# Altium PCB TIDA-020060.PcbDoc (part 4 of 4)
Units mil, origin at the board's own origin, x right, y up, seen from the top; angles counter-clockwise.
Board outline 2114.94 x 3612.21 mil, 4 copper layers (Top Layer, Signal Layer 1, Signal Layer 2, Bottom Layer), stack 61.811 mil thick; 272 components, 167 nets, 840 pads, 352 vias.
Unrouted connection lines stored in the file: 261.
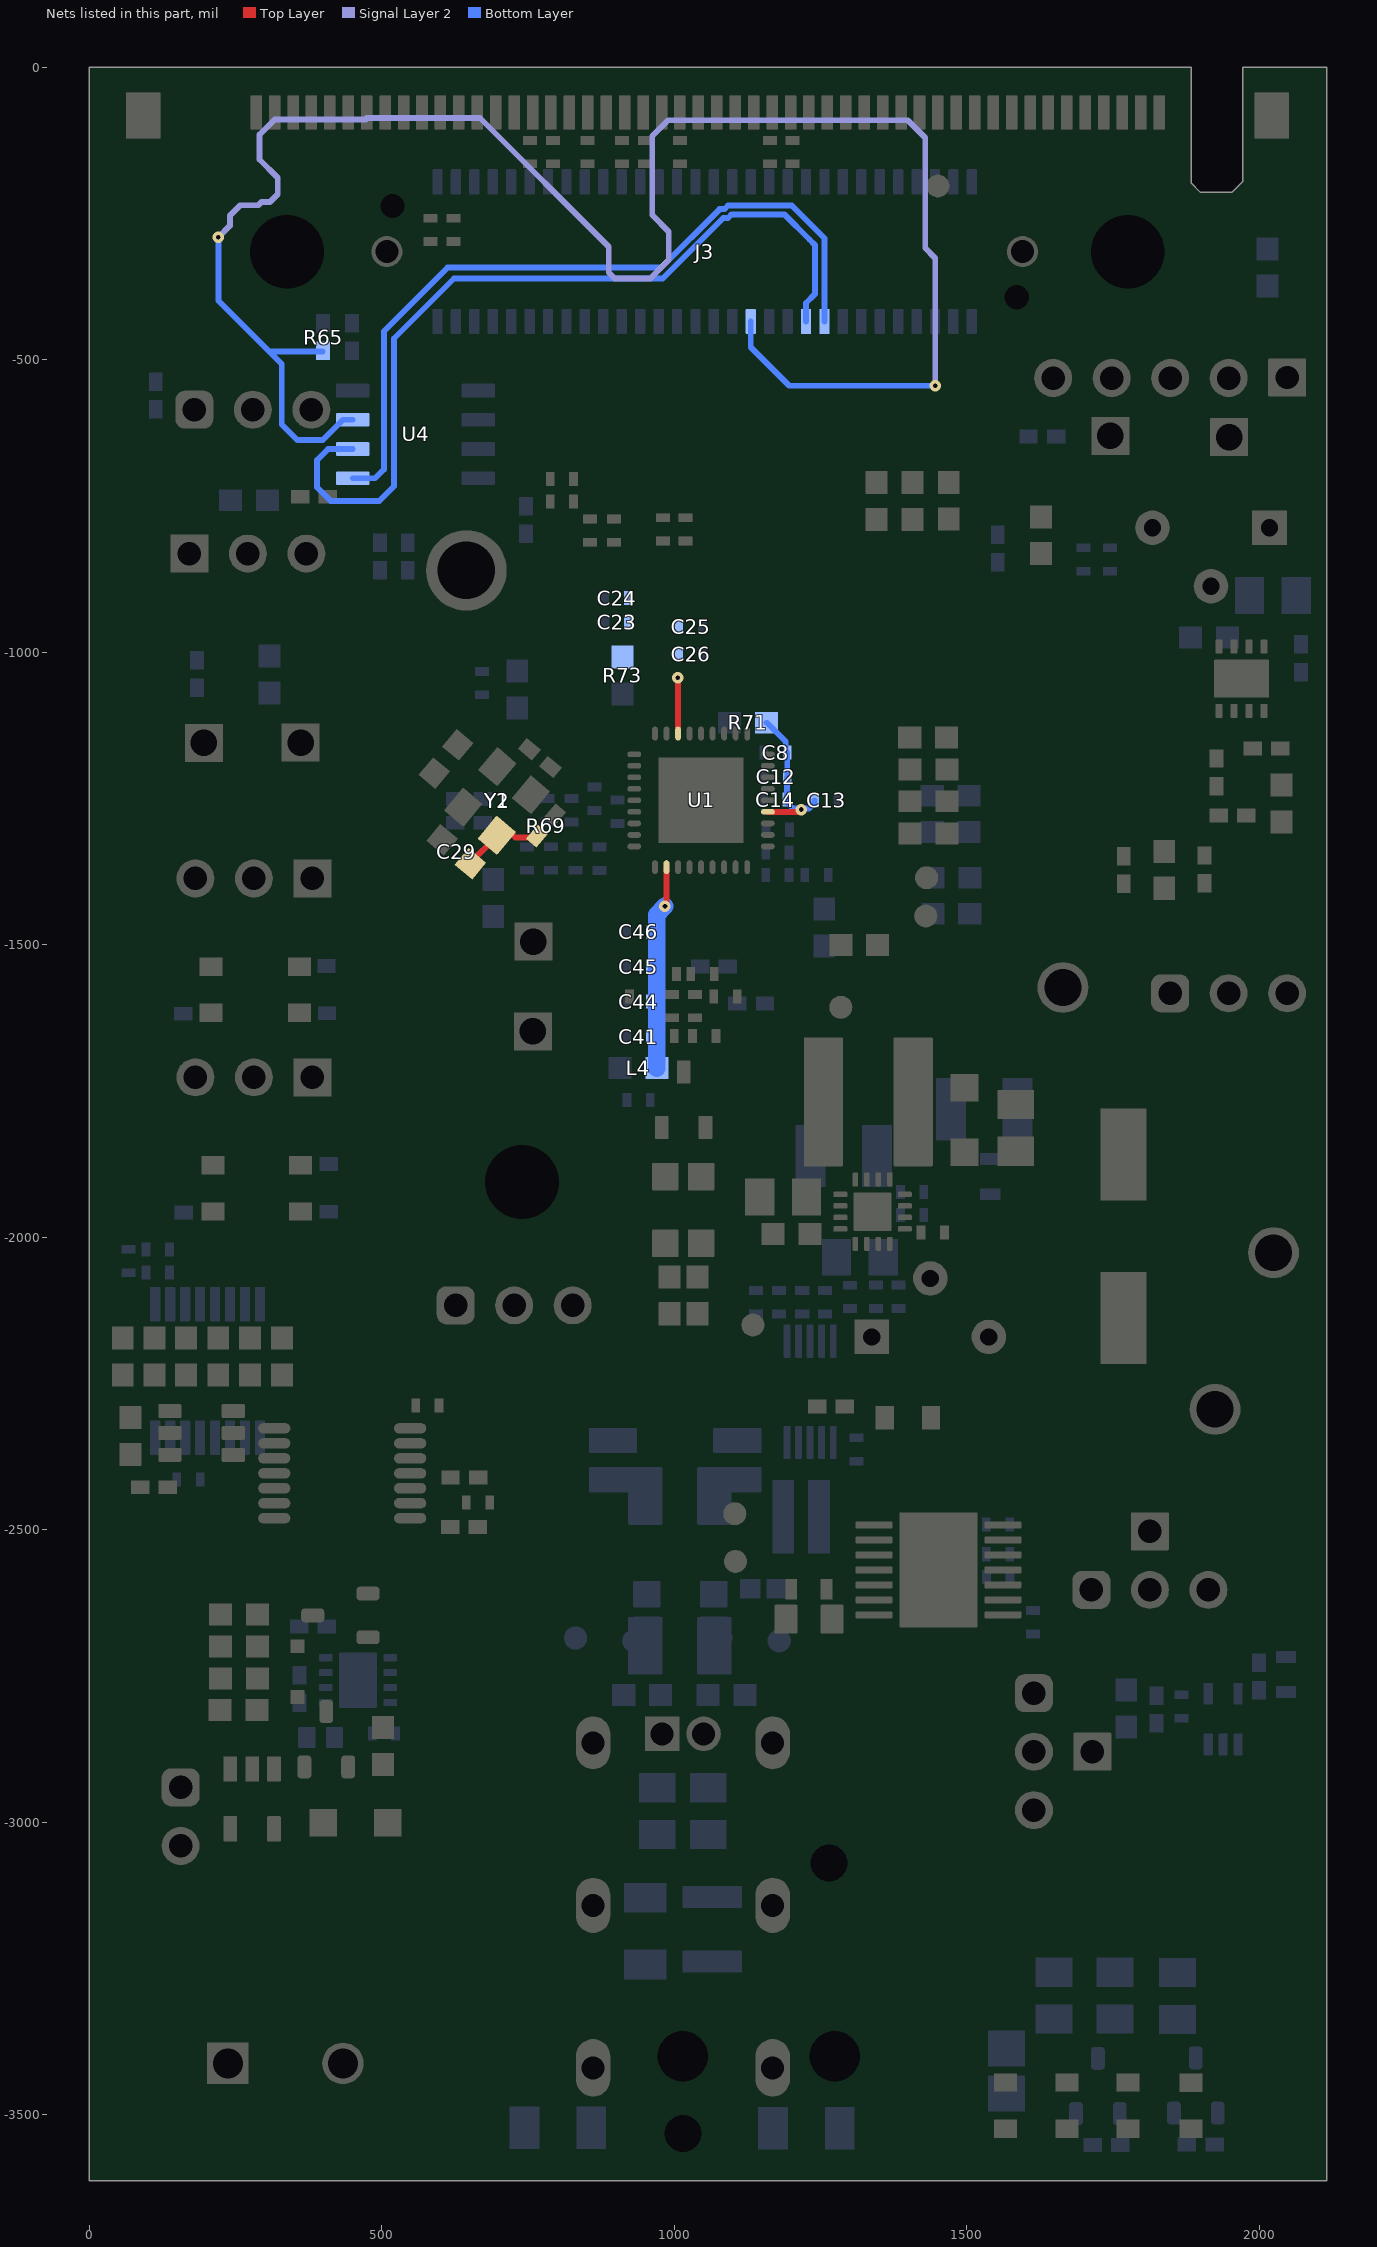
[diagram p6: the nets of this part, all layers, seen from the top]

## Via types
v1: diameter 19.68, hole 7.87, Top Layer to Bottom Layer, tented both sides, 333 vias
v2: diameter 19.68, hole 7.87, Top Layer to Bottom Layer, 10 vias
v3: diameter 20, hole 10, Top Layer to Bottom Layer, 7 vias
v4: diameter 50, hole 28, Top Layer to Bottom Layer, 2 vias

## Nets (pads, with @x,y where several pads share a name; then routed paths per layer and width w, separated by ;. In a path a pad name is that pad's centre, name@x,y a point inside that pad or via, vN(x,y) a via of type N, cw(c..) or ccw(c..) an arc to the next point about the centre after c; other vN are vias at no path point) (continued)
VDDA3P3_P11: C41.1 C44.1 C45.1 C46.2 L4.2 U1.11 | length 352
  Top Layer w6: v1(983.84,-1434.11) v1@984.98,-1432.97
  Top Layer w10: v1(983.84,-1434.11) 983.84,-1431.49 986.52,-1428.81 U1.11@986.52,-1367.03
  Bottom Layer w30: L4.2@970.09,-1710.47 970.06,-1656.58 ; 970.04,-1656.56 970.04,-1477.58 969.9,-1477.44 969.9,-1448.05 v1(983.84,-1434.11)
VDDIO_P22: C8.1 C12.1 C13.1 C14.2 R71.2 U1.22 | length 272.3
  Top Layer w10: U1.22@1159.75,-1272.54 1210.13,-1272.54 1214.14,-1268.54 v1(1216.76,-1268.54)
  Bottom Layer w10: R71.2@1157.2,-1120.21 1158.18,-1120.21 1190.32,-1152.35 1190.32,-1168.73 C8.1@1192.82,-1171.23 1192.9,-1171.31 1192.9,-1212.49 C12.1@1192.98,-1212.57 1192.56,-1213 1192.56,-1251.32 C14.2@1192.14,-1251.75 1192.14,-1256.25 1202.58,-1266.69 1214.9,-1266.69 v1(1216.76,-1268.54) 1218.61,-1266.69 1230.33,-1266.69 1239.73,-1257.29 C13.1@1239.73,-1252.79
VDDIO_P34: C23.1 C24.1 C25.1 C26.2 R73.2 U1.34 | length 95.4
  Top Layer w10: v1(1005.69,-1043.53) 1006.13,-1043.96 U1.34@1006.21,-1138.68 U1.34@1006.21,-1138.68
WKUP_I2C0_SCL: J3.21 U4.6 | length 1485.4
  Bottom Layer w10: U4.6@450.14,-652.42 408.12,-652.42 389.17,-671.37 389.17,-717.8 412.6,-741.23 495.41,-741.23 520.77,-715.86 520.77,-463.46 623.41,-360.82 980,-360.82 1083.5,-257.32 1091.77,-257.32 1097.85,-251.24 1187.96,-251.24 1230.81,-294.09 1240.07,-303.35 1240.07,-387.6 1224.96,-402.71 J3.21@1224.96,-434.25
WKUP_I2C0_SDA: J3.22 U4.5 | length 1302.9
  Bottom Layer w10: U4.5@450.14,-702.42 488.07,-702.42 503.43,-687.05 503.43,-451.11 612.36,-342.18 977.43,-342.18 1077.29,-242.32 1085.55,-242.32 1091.64,-236.24 1200.65,-236.24 1256.46,-292.04 J3.22@1256.46,-434.25
WP: J3.18 R65.1 U4.7 | length 3255.1
  Signal Layer 2 w10: v1(220.52,-290.39) 240.14,-270.77 240.14,-253.45 257.9,-235.69 288.68,-235.69 294.51,-229.86 309.01,-229.86 322.02,-216.85 322.02,-188.43 290.87,-157.28 290.87,-114.89 316.77,-88.98 471.72,-88.98 474.05,-86.65 667.8,-86.65 887.84,-306.69 887.84,-350.68 897.99,-360.82 958.79,-360.82 990.38,-329.23 990.38,-280.73 962.04,-252.39 962.04,-117.25 988.86,-90.43 1399,-90.43 1428.69,-120.12 1428.69,-308.87 1445.94,-326.12 1445.94,-543.97 v1(1446.15,-544.18)
  Bottom Layer w10: v1(220.52,-290.39) 220.52,-398.64 307.56,-485.68 ; R65.1@398.33,-485.68 307.56,-485.68 ; U4.7@450.14,-602.42 433.41,-602.42 398.83,-637 355.5,-637 328.81,-610.32 328.81,-506.93 307.56,-485.68 ; J3.18@1130.47,-434.25 1130.47,-478.54 1196.1,-544.18 v1(1446.15,-544.18)
XO_combined: C29.1 R69.2 Y1.3 Y2.3 | length 139.5
  Top Layer w10: C29.1@651.24,-1360.95 651.24,-1359.59 696.32,-1314.51 Y1.3@696.32,-1312.51 697.2,-1311.63 723.56,-1311.63 728.47,-1316.54 762.73,-1316.54 R69.2@765.26,-1314.01
pads on no net: H1.1 H2.1 H13.1 J1.MH1 J1.MH2 J1.MH3 J1.MH4 J2.10 J2.14 J2.16 J2.34 J2.36 J2.38 J2.40 J2.52 J2.76 J2.78 J2.80 J2.82 J2.99 J3.2 J3.3 J3.5 J3.6 J3.8 J3.9 J3.11 J3.12 J3.19 J3.39 J3.40 J3.46 J3.48 J3.49 J3.50 J3.52 J3.53 J3.57 J3.58 J3.59 J3.ALIGN1 J3.ALIGN2 LBL4.0 R38.3 R96.3 SH-J1.0 SH-J2.0 SH-J3.0 SH-J5.0 U3.2 U3.7 U8.1 U8.2 U8.3 U8.11 U8.12 U8.13 U10.12 U10.15 U10.17 U13.11
copper on no net:
  other v2: 1315.98,-1978.81 1361.65,-1978.81 1338.81,-1955.97 1315.98,-1933.14 1361.65,-1933.14

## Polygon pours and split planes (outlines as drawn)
GND on Bottom Layer "NONET_L-01_P-001" (solid, pour order 288): -472.91,356.33 -472.91,-3945.38 2594.42,-3945.38 2594.42,356.33
PoDL_D- on Bottom Layer "Bottom Layer-PoDL_D-" (solid, pour order 249): 1044.07,-2631.56 1044.66,-2632.16 1097.01,-2632.16 1111.73,-2617.43 1149.03,-2617.43 1149.03,-2558.89 1204.75,-2503.17 1204.75,-2411.34 1186.11,-2392.7 1040.95,-2392.7 1038.88,-2394.77 1039.1,-2394.99 1039.1,-2584.55 1043.47,-2588.92 1043.47,-2630.12
+6V on Bottom Layer "NONET_L-01_P-001" (solid, pour order 255): 383.54,-2873.5 383.54,-2831.53 414.4,-2800.66 415.21,-2800.66 415.21,-2791.55 415.78,-2790.98 413.83,-2789.03 394.11,-2789.03 384.62,-2779.54 347.24,-2779.54 347.24,-2833.02 344.17,-2836.1 344.17,-2873.5
GND_WIRE on Bottom Layer "BOTTOM_LAYER_GND_WIRE_P191" (solid, pour order 191): 1210.02,-3591.15 1210.02,-2818.13 829.21,-2818.13 829.21,-3591.15
GND on Bottom Layer "BOTTOM_LAYER_GND_P190" (solid, pour order 190): 1132.67,-3201.59 1132.67,-3310.02 1092.28,-3350.41 941.7,-3350.41 898.69,-3307.4 898.69,-3202.09
TERM on Bottom Layer "BOTTOM_LAYER_TERM_P189" (solid, pour order 189): 933.61,-2990.57 901.33,-3023.75 901.33,-3149.12 914.3,-3162.08 1117.45,-3162.08 1126.34,-3153.19 1126.34,-3021.48 1095.42,-2990.57
+3V3 on Bottom Layer "BOTTOM_LAYER_+3V3_P217" (solid, pour order 217): 1848.56,-947.98 1847.94,-948.6 1569.34,-948.6 1546.46,-925.72 1546.46,-885.52 1573.36,-858.62 1841.14,-858.62 1861.23,-878.72 1861.23,-935.61
+3V3 on Bottom Layer "NONET_L-01_P-001" (solid, pour order 285): 1825.5,-1072.05 1811.07,-1057.62 1668.42,-1057.62 1655.15,-1070.89 1655.15,-1161.47 1666.94,-1173.26 1811.22,-1173.26 1825.02,-1159.46
PSE_boost_out on Bottom Layer "NONET_L-01_P-001" (solid, pour order 271): 1561.1,-1727.86 1681.28,-1727.86 1698.3,-1744.88 1698.3,-1819.8 1684.68,-1833.42 1613.03,-1833.42 1612.29,-1834.16 1561.1,-1834.16
+3V3 on Bottom Layer "NONET_L-01_P-001" (solid, pour order 270): 119.29,-2312.66 121.24,-2314.61 121.24,-2369.77 153.48,-2402.01 156.9,-2402.01 156.9,-2426.01 116.84,-2426.01 78.53,-2387.7 78.53,-2323.43 89.3,-2312.66
+3V3 on Bottom Layer "NONET_L-01_P-001" (solid, pour order 269): 119.29,-2143.37 121.24,-2141.42 121.24,-2086.26 104.32,-2069.35 104.32,-2047.93 83.43,-2047.93 78.49,-2052.87 54.49,-2052.87 54.49,-2067.87 103.52,-2116.9 103.52,-2141.42 105.47,-2143.37
NetC61_1 on Bottom Layer "NONET_L-01_P-001" (solid, pour order 268): 1395.31,-2088.94 1371.31,-2088.94 1371.31,-2073.94 1362.68,-2065.31 1332.16,-2065.31 1332.16,-2002.31 1386.91,-2002.31 1408.28,-2023.68 1408.28,-2075.97
PSE_BOOST_VIN on Bottom Layer "Bottom Layer-PSE_BOOST_VIN" (solid, pour order 266): 1161.43,-1921.23 1210.9,-1970.7 1210.9,-2034.1 1223.03,-2046.23 1246.86,-2046.23 1252.16,-2040.93 1252.16,-1910.39 1221.16,-1879.39 1221.16,-1658.07 1181.21,-1658.07 1161.43,-1677.86
PoDL_D+ on Bottom Layer "NONET_L-01_P-001" (solid, pour order 228): 853.14,-2726.57 853.14,-2647.83 868.81,-2632.16 974.5,-2632.16 979.22,-2627.44 979.22,-2394.16 977.48,-2392.43 855.7,-2392.43 853.4,-2394.73 853.4,-2420.28 855.7,-2503.92 770.46,-2503.22 770.46,-2706.88 790.15,-2726.57 813.77,-2726.57
VDDIO_P34 on Bottom Layer "BOTTOM_LAYER_VDDIO_P34_P162" (solid, pour order 162): 909.34,-890.65 909.34,-964.14 899.83,-973.65 880.87,-973.65 874.05,-980.47 874.05,-1086.82 883.93,-1096.7 920.16,-1096.7 929.1,-1087.76 929.1,-1045.18 933.1,-1041.18 979.69,-1041.18 996.63,-1058.12 1019.93,-1058.12 1025.1,-1052.94 1024.63,-1052.47 1024.63,-918.59 1013.1,-907.06 980.81,-907.06 964.4,-890.65
+12V_conn on Bottom Layer "BOTTOM_LAYER_+12V_CONN_P169" (solid, pour order 169): 1776.45,-121.23 1776.45,-332.62 2066.44,-332.62 2066.44,-264.11 1922.18,-119.87
+3.3V_conn on Bottom Layer "BOTTOM_LAYER_+3.3V_CONN_P187" (solid, pour order 187): 1342.66,-174.59 1342.66,-273.62 1368.67,-299.64 1511.39,-299.64 1627.03,-415.28 1653.78,-415.28 1665.19,-403.87 1665.19,-283 1611.49,-229.3 1405.23,-229.3 1390.73,-214.8 1390.73,-174.59
+12V_conn on Bottom Layer "BOTTOM_LAYER_+12V_CONN_P182" (solid, pour order 182): 1405.65,-455.33 1405.65,-411.18 1369,-374.53 1369,-322.69 1385.22,-306.47 1440.56,-306.47 1460.92,-326.82 1460.92,-407.92 1453.72,-415.12 1453.72,-455.33
+12V on Bottom Layer "BOTTOM_LAYER_+12V_P172" (solid, pour order 172): 2032.7,-354.04 2058.83,-380.17 2058.83,-465.68 2044.27,-480.24 1986.71,-480.24 1972.83,-466.36 1972.83,-372.91 1976.42,-372.91 1995.3,-354.04
GND on Top Layer "NONET_L-01_P-001" (solid, remove dead copper, pour order 283): -407.23,461 -419.41,448.82 -419.41,-4297.83 2541.91,-4297.83 2541.91,448.82
GND_WIRE on Top Layer "TOP_LAYER_GND_WIRE_P210" (solid, pour order 210): 729.23,-2727.4 729.23,-3602.48 1431.05,-3602.48 1431.05,-2727.4
NetQ2_1 on Top Layer "NONET_L-01_P-001" (solid, pour order 251): 288.03,-2856.46 286.06,-2858.43 286.06,-2874.17 281.14,-2879.1 281.14,-2885.99 310.68,-2885.99 315.58,-2881.08 315.58,-2858.43 313.62,-2856.46
+3.3V_conn on Top Layer "TOP_LAYER_+3.3V_CONN_P247" (solid, pour order 247): 1775.23,-47.87 1724.05,-47.87 1724.05,-106.13 1718.1,-112.09 1718.1,-169.95 1678.6,-209.44 1577.37,-209.44 1526.07,-260.74 1526.07,-471.61 1544.28,-489.82 1544.28,-735.42 1596.87,-788.01 1645.45,-788.01 1645.47,-788.03 1660.9,-788.03 1684.73,-764.2 1684.73,-584.98 1724.53,-545.18 1724.53,-259.64 1780.66,-203.51 1780.66,-111.56 1775.23,-106.13
ext_pwr_supply on Top Layer "NONET_L-01_P-001" (solid, pour order 275): 1696.52,-2569.96 1680.28,-2586.2 1680.28,-2693.28 1755.35,-2768.35 2033.67,-2768.35 2094.81,-2707.2 2094.81,-1701.51 2047.17,-1653.86 1922.5,-1653.86 1893.91,-1625.27 1893.91,-1558.57 1874.46,-1539.12 1820.86,-1539.12 1802.2,-1557.78 1802.2,-1725.33 1849.05,-1772.18 1849.05,-2237.36 1968.16,-2356.47 1968.16,-2642.09 1940.37,-2669.88 1794.26,-2669.88 1794.26,-2667.69 1745.24,-2618.68 1745.24,-2586.2 1729,-2569.96
PSE_BOOST_VIN on Top Layer "NONET_L-01_P-001" (solid, pour order 267): 1288.09,-1876.53 1286.08,-1878.54 1181.06,-1878.54 1161.66,-1859.15 1161.66,-1669.35 1172.94,-1658.07 1286.08,-1658.07 1288.09,-1660.08
PSE_boost_out on Top Layer "NONET_L-01_P-001" (solid, pour order 263): 1472.26,-1720.37 1472.26,-1767.61 1521.91,-1767.61 1551.89,-1797.59 1614.89,-1797.59 1708.45,-1891.15 1708.45,-1937.14 1806.75,-1937.14 1806.75,-1779.66 1728.01,-1779.66 1695.94,-1747.59 1546.72,-1747.59 1519.5,-1720.37
NetD12_2 on Top Layer "NONET_L-01_P-001" (solid, pour order 262): 1343.93,-1910.68 1343.93,-1888.72 1402.05,-1830.6 1519.5,-1830.6 1519.5,-1877.85 1455.88,-1877.85 1421.12,-1912.61 1345.45,-1912.61
PoDL_D+ on Top Layer "NONET_L-01_P-001" (solid, pour order 257): 1370.65,-2548.71 1372.6,-2546.76 1372.6,-2487.67 1370.65,-2485.72 1331.15,-2485.72 1302.57,-2457.14 1283.14,-2457.14 1276.07,-2464.21 1276.07,-2537.54 1287.25,-2548.71
High_side_sw_VIN on Top Layer "NONET_L-01_P-001" (solid, pour order 256): 1370.65,-2588.08 1372.6,-2590.03 1372.6,-2649.13 1370.65,-2651.08 1329.16,-2651.08 1298.51,-2681.72 1277.75,-2681.72 1269.84,-2673.82 1249.84,-2673.82 1249.84,-2584.01 1249.87,-2583.98 1307.45,-2583.98 1311.56,-2588.08
NetC52_1 on Top Layer "NONET_L-01_P-001" (solid, pour order 253): 157.31,-2306.68 155.3,-2308.69 119.94,-2308.69 117.94,-2306.68 117.94,-2287.08 85.52,-2254.66 38.25,-2254.66 38.25,-2215.29 184.11,-2215.29 184.11,-2254.66 157.31,-2281.46 157.31,-2287.08
NetC53_1 on Top Layer "NONET_L-01_P-001" (solid, pour order 252): 228.21,-2308.69 226.2,-2306.68 226.2,-2287.08 201.56,-2262.43 201.56,-2215.29 348.15,-2215.29 348.15,-2254.66 297.99,-2254.66 265.57,-2287.08 265.57,-2306.68 263.57,-2308.69
+3V3 on Top Layer "TOP_LAYER_+3V3_P185" (solid, pour order 185): 1580.44,-811.63 1546.55,-845.52 1546.55,-927.25 1562.21,-942.91 1638.42,-942.91 1670.33,-910.99 1670.33,-818.53 1663.44,-811.63
+1V0 on Top Layer "TOP_LAYER_+1V0_P179" (solid, pour order 179): 1818.62,-1359.83 1818.68,-1359.77 1818.68,-1253.76 1826.56,-1245.89 1878.38,-1245.89 1885.15,-1252.66 1885.15,-1291.8 1856.02,-1320.94 1856.02,-1359.83
+1V0_reg on Top Layer "TOP_LAYER_+1V0_REG_P170" (solid, pour order 170): 1919.09,-1083.89 1917.2,-1085.78 1917.2,-1155.9 1949.99,-1188.69 1949.99,-1298.37 1944.48,-1303.89 1893.06,-1303.89 1880.09,-1316.85 1880.09,-1366.04 1887.47,-1373.41 1999.25,-1373.41 2003.72,-1368.94 2001.71,-1366.93 2001.71,-1265.88 2011.99,-1255.6 2060.95,-1255.6 2066.77,-1249.78 2066.77,-1201.94 2058.49,-1193.67 2019.82,-1193.67 2011.32,-1185.17 2011.32,-1150.3 2005.29,-1144.26 1977.34,-1144.26 1968.4,-1135.32 1968.4,-1122.57 1961.9,-1116.07 1949.99,-1116.07 1944.9,-1110.98 1944.9,-1086.67 1942.12,-1083.89
+12V_conn on Top Layer "TOP_LAYER_+12V_CONN_P168" (solid, pour order 168): 1818.54,-47.87 1818.54,-109.15 1785.32,-142.37 1785.32,-181.03 1800.23,-195.94 1848.36,-195.94 1876,-168.3 1876,-55.72 1867.93,-47.65
GND on Signal Layer 1 "NONET_L-01_P-001" (solid, pour order 284): -413.51,293.43 -413.51,-4008.29 2653.81,-4008.29 2653.81,293.43
+12V on Signal Layer 1 "Signal Layer 1-+12V" (solid, pour order 282): 2093.15,-1695.3 2093.15,-1559.16 2075.76,-1541.77 2025.45,-1541.77 2002.14,-1565.08 2002.14,-1663.11 1955.53,-1709.72 1853.19,-1709.72 1853.19,-707.82 2099.09,-461.92 2099.09,-348.27 1617.39,-352.76 1617.39,-2260.9 1853.19,-2496.7 1853.19,-3000.81 1536.31,-3317.68 1100.99,-3317.68 623.43,-2840.12 535.14,-2840.12 520.87,-2854.39 520.87,-3332.01 801.07,-3612.21 1565.38,-3612.21 2054.67,-3122.92 2054.67,-2464.98 1853.19,-2263.5 1853.19,-1825.89 1962.56,-1825.89
+12V on Signal Layer 1 "SIGNAL_LAYER_1_+12V_P184" (solid, pour order 184): 1626.03,-352.77 1496.26,-482.54 1496.26,-649.17 1626.03,-778.94
+12V_conn on Signal Layer 1 "SIGNAL_LAYER_1_+12V_CONN_P188" (solid, pour order 188): 1401.57,-402.33 1369,-369.76 1369,-256.43 1440.83,-184.6 1701.57,-184.6 1765.04,-121.13 1842.89,-121.13 1862.95,-141.2 1862.18,-141.96 1862.18,-189.29 1823.51,-227.96 1632.17,-227.96 1511.9,-348.23 1457.8,-402.33
+3V3 on Signal Layer 2 "NONET_L-01_P-001" (solid, pour order 287): -688.18,351.66 -688.18,-4166.92 2581.48,-4166.92 2581.48,361.61
+6V on Signal Layer 2 "NONET_L-01_P-001" (solid, pour order 272): 579.27,-2795.11 579.27,-2815.05 552.92,-2841.39 465.88,-2841.39 455.3,-2851.98 452.92,-2851.98 343.21,-2961.69 312.33,-2961.69 305.2,-2954.56 305.2,-2936.21 316.21,-2925.19 316.21,-2856.73 300.23,-2840.75 300.23,-2711.81 309.52,-2702.53 342.13,-2702.53 358.98,-2719.37 377.77,-2719.37 444.18,-2785.79 569.95,-2785.79
+1V0 on Signal Layer 2 "SIGNAL_LAYER_2_+1V0_P171" (solid, pour order 171): 1826.56,-1245.89 1818.62,-1253.82 1818.62,-1292.15 1758.14,-1352.63 525.44,-1352.63 496.62,-1381.45 496.62,-1466.41 590.98,-1560.77 1680.3,-1560.77 1885.15,-1355.91 1885.15,-1252.95 1878.34,-1246.13 1878.34,-1245.89
GND on Signal Layer 2 "SIGNAL_LAYER_2_GND_P219" (solid, pour order 219): 693.87,-311.19 585.5,-419.57 585.5,-730.31 619.78,-730.31 786.76,-897.3 790.08,-893.98 1128.47,-893.98 1294.66,-1060.17 1294.66,-1106.24 1208.16,-1106.24 1173.81,-1140.59 1173.81,-1225.74 1189.3,-1225.74 1255.65,-1292.09 1420.42,-1292.09 1531.01,-1181.51 1531.01,-962.55 1251.22,-682.76 1169.39,-682.76 1055.49,-568.86 1244.59,-379.76 1244.59,-182.91 1213.63,-151.95 1212.52,-153.06 974.76,-153.06 819.94,-307.88 707.14,-307.88
ext_pwr_supply on Signal Layer 2 "Signal Layer 2-+12V" (solid, pour order 240): 497.74,-3508.77 924.33,-3508.77 1752.65,-2680.45 1752.65,-2595.5 1673.69,-2516.54 1518.72,-2516.54 1441.23,-2594.03 893.47,-3141.79 336.55,-3141.79 336.55,-3458.4 386.92,-3508.77
PSE_BOOST_VIN on Signal Layer 2 "NONET_L-01_P-001" (solid, pour order 274): 1167.32,-1663.68 1161.66,-1669.35 1161.66,-1859.15 1181.06,-1878.54 1286.91,-1878.54 1287.5,-1877.95 1475.74,-1877.95 1623.54,-1730.15 1923.25,-1730.15 1997.61,-1655.78 1997.61,-1559.86 1978.66,-1540.9 1978.23,-1541.33 1927.39,-1541.33 1902.83,-1565.89 1902.83,-1627.93 1868.86,-1661.9
PSE_boost_out on Signal Layer 2 "NONET_L-01_P-001" (solid, pour order 273): 1621.48,-1747.73 1627.58,-1741.62 1763.2,-1741.62 1769.92,-1748.34 1769.92,-2068.88 1957.61,-2256.57 1957.61,-2433.46 1843.44,-2547.63 1782.03,-2547.63 1769.92,-2535.51 1769.92,-2445.8 1621.48,-2297.36
High_side_sw_VIN on Signal Layer 2 "Signal Layer 2-High_side_sw_VIN" (solid, pour order 261): 1327.7,-2648.63 1474.49,-2501.84 1679.44,-2501.84 1760.03,-2582.43 1767.53,-2582.43 1767.53,-2624.02 1792.83,-2649.31 1833.98,-2649.31 1856.92,-2626.38 1856.92,-2576 1836.77,-2555.85 1790.25,-2555.85 1769.92,-2535.51 1769.92,-2469.27 1678.18,-2377.54 1414.94,-2377.54 1328.12,-2464.36 1328.12,-2550.09 1307.11,-2571.1 1259.87,-2571.1 1259.87,-2683.6 1273.62,-2697.35 1312.84,-2697.35 1327.35,-2682.83
PoDL_D+ on Signal Layer 2 "NONET_L-01_P-001" (solid, pour order 258): 815.09,-2491.9 815.09,-2567.9 842.43,-2595.24 1204.14,-2595.24 1247.61,-2551.77 1313.67,-2551.77 1321.24,-2544.2 1321.24,-2436.33 1317.48,-2432.56 874.42,-2432.56

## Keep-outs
Keep-Out Layer:
  pour cut-out: 1884.39,1.16 1882.67,-0.56 1882.67,-197.63 1897.92,-212.89 1898.97,-211.84 1953.71,-211.84 1971.39,-194.16 1971.39,2.16
  text ".Layer_Name" at 341.86,-3937.58 h60

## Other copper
Top Layer:
  pour cut-out: 372.78,-99.02 372.78,-252.78 369.4,-256.17 397.62,-284.39 397.62,-614.74 580.49,-797.61 755.53,-797.61 755.53,-803.74 970.73,-1018.93 970.73,-1107.8 1009.95,-1147.02 1151.61,-1147.02 1151.61,-1249.6 1158.85,-1256.83 1320.95,-1256.83 1364.31,-1213.48 1364.31,-1016.4 1537.27,-843.43 1537.27,-510.35 1438.02,-411.09 1392.9,-411.09 1392.9,-164.42 1327.5,-99.02
  pour cut-out: 1031.36,-1355.11 1001.25,-1355.11 1001.25,-1434.3 983.43,-1452.13 983.43,-1534.62 957.34,-1560.71 957.34,-1732.96 922.97,-1767.32 922.97,-2207.22 965.12,-2249.36 965.12,-2761 920.39,-2805.72 920.39,-2898.45 934.54,-2912.6 1088.24,-2912.6 1103.95,-2896.89 1103.95,-2799.12 1065.77,-2760.94 1065.77,-2244.47 1104.88,-2205.36 1104.88,-1754.46 1076.99,-1726.57 1076.99,-1558.09 1050.48,-1531.58 1050.48,-1452.12 1031.36,-1433
  text ".Layer_Name" at 341.86,-3937.58 h60
Bottom Layer:
  pour cut-out: 1209.71,-1160.1 1231.29,-1138.52 1337.04,-1138.52 1352.56,-1123 1352.02,-1122.45 1352.02,-1053.75 1318.55,-1020.28 1265.26,-1020.28 1234.32,-989.34 1216.71,-1006.95 1216.71,-1039.93 1201.57,-1055.07 1110.09,-1055.07 1068.04,-1013.03 1068.04,-953.66 1032.22,-917.84 1032.22,-874.96 1073.42,-833.76 1073.42,-662.55 1098.48,-637.49 1170.8,-637.49 1197.2,-663.9 1265.65,-663.9 1327.18,-725.43 1327.18,-771.97 1529.06,-973.85 1529.06,-1135.09 1525.78,-1135.09 1409.4,-1251.47 1308.22,-1251.47 1299.38,-1242.63 1228.57,-1242.63 1209.17,-1223.23
  pour cut-out: 1006.65,-473.83 823.64,-656.84 823.64,-813.51 862.46,-852.33 1029.52,-852.33 1052.05,-829.8 1052.05,-732.4 970.95,-651.29 970.95,-634.31 1054.48,-550.78 1054.48,-524.43
  pour cut-out: 532.56,-115.86 496.84,-115.86 408.56,-204.14 408.56,-297 423.42,-311.85 439.7,-311.85 451.99,-299.57 657.98,-299.57 719.4,-238.14 787.68,-238.14 799.11,-226.71 799.11,-160.72 798.25,-160.72 752.26,-114.72
  pour cut-out: 1105.51,-239.67 990.35,-354.84 990.35,-396.81 1011.33,-417.8 1186.57,-417.8 1231.96,-372.42 1231.96,-277.71 1193.66,-239.41
  text ".Layer_Name" at 341.86,-3937.58 h60

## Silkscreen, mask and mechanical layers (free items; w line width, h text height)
Top Overlay:
  drawing of 169 lines, arcs and shapes, not listed
  text "RESET" at 1304.93,-171.7 h55
  text "100" at 306.67,-225.6 h70 r90
  text "2" at 1836.59,-237.5 h70 r90
  text "MDIO" at 1667.2,-455.22 h50 r90
  text "PoDL PSE" at 683,-459.57 h120
  text "MDC" at 2077.43,-461.74 h50 r90
  text "TIDA-020060" at 656.2,-578.84 h100
  text "RX_D0" at 1502.34,-595.84 h68.9 r90
  text "RX_D2" at 1379.97,-596.57 h68.9 r90
  text "RX_D1" at 1443.33,-596.57 h68.9 r90
  text "WAKE PU" at 84.81,-634.4 h65 r90
  text "WAKE PD" at 506.39,-638.38 h65 r90
  text "rev. E2" at 965.04,-659.11 h80
  text "D" at 1626.33,-662.91 h50
  text "C" at 2035.36,-663.32 h50
  text "PU" at 1365.23,-671.4 h59.06 r90
  text "PU" at 1429.25,-672.05 h59.06 r90
  text "PU" at 1487.6,-671.4 h59.06 r90
  text "EN" at 238.35,-737.86 h68.9
  text "SGMII" at 856.71,-739.48 h60
  text "MAC STRAP" at 1301.95,-827.52 h68.9 r90
  text "ENABLE" at 92.65,-972.52 h80 r90
  text "VSLEEP" at 501.76,-973.53 h80 r90
  text "INH" at 123.21,-1079.31 h80
  text "INT" at 319.29,-1079.86 h80
  text "PHY ID / STRAP" at 1401.01,-1104.72 h68.9
  text "1.0V LDO" at 2083.31,-1134.75 h50 r90
  text "RX_" at 1598.31,-1158.58 h59.06
  text "PU" at 1503.19,-1165.89 h59.06
  text "PD" at 1502.96,-1215.88 h59.06
  text "CTRL" at 1598.31,-1215.96 h59.06
  text "PIN 7" at 298.46,-1243.78 h60 r90
  text "PU" at 1504.57,-1277.14 h59.06
  text "STRP_1" at 1603.18,-1297.87 h59.06
  text "PD" at 1504.34,-1327.13 h59.06
  text "ATP0" at 1453.15,-1405.12 h59.06
  text "+3V3" at 715.38,-1434.43 h40
  text "DUT" at 1677.35,-1462.32 h45
  text "REG" at 1855.75,-1463.67 h45
  text "STRP / _DFT" at 1452.28,-1521.36 h59.06
  text "AUTO" at 91.61,-1573.62 h80 r90
  text "CLKOUT" at 1314.86,-1629.42 h68.9
  text "MANAGED" at 519.19,-1638.15 h75 r90
  text "STRP_1" at 1783.82,-1648.94 h50 r90
  text "GND" at 724.6,-1738.62 h40
  text "EXT." at 1865.75,-1757.73 h70 r90
  text "+12V" at 2070.1,-1770.7 h70 r90
  text "BOOST" at 1984.32,-1816.37 h45 r90
  text "PWR supply" at 1942.81,-1854.8 h45 r90
  text "+1V0" at 1961.85,-1943.48 h59.06
  text "Host (M)" at 506.76,-1965.46 h80 r90
  text "Client (S)" at 92.49,-1970.43 h80 r90
  text "SoC" at 668.92,-2296.43 h60 r90
  text "DETEC- / TION" at 770.06,-2335.39 h50 r90
  text "AUTO" at 849.6,-2342.75 h60 r90
  text "Power on SPE active" at 1021.21,-2399.25 h70
  text "Boost" at 1837.14,-2411.11 h70 r90
  text "Shunt-" at 913.18,-2491.38 h60
  text "VID" at 183,-2509.43 h60
  text "EXTERNAL" at 1737.94,-2549.19 h70 r90
  text "+12V" at 1937.3,-2550.11 h70 r90
  text "HSS" at 1274.29,-2555.15 h60 r90
  text "Shunt+" at 913.18,-2568.48 h60
  text "BOOST_OUT" at 2074.71,-2693.06 h60 r90
  text "PSE PWR SRC" at 1632.07,-2702.94 h60
  text "ON" at 1671,-2800.4 h70
  text "SoC" at 1809.08,-2900.31 h70
  text "HSS EN" at 1527.53,-2990 h70 r90
  text "detect" at 1670.09,-2999.79 h70
  text "max. 36V" at 160.58,-3221.63 h90
  text "12V avail." at 1584.53,-3397.01 h59.06 r90
  text "6V avail." at 1684.33,-3397.01 h59.06 r90
  text "3.3V avail." at 1793,-3397.01 h59.06 r90
  text "1.0V avail." at 1898.49,-3397.01 h59.06 r90
  text "GND" at 104.93,-3491.69 h80 r90
  text "VIN" at 634.79,-3495.63 h80 r90
  text ".Layer_Name" at 341.86,-3937.58 h60
Bottom Overlay:
  lines w6: 829.05,-830.94 829.05,-660.7 1102.91,-660.7 1102.91,-830.94 829.05,-830.94 ; 1301.1,-1483.12 1301.1,-1208.37 1865.62,-1208.37 1865.62,-1483.12 1301.1,-1483.12
  lines w10: 22.22,-2099.46 21.7,-2099.46 21.7,-2457.76 338.25,-2457.76 338.25,-1992.74 25.83,-1992.74 ; 1177.83,-2152.27 1108.65,-2152.27 1108.65,-2083.74 911.57,-2083.74 911.57,-1939.52 1140.96,-1939.52 1140.96,-1857.62 1167.71,-1857.62 1167.71,-1775.07 1364.79,-1775.07 1364.79,-1677.92 1648.32,-1677.92 1648.32,-1969.16 1592.8,-1969.16 1592.8,-2213.03 1292.36,-2213.03 1292.36,-2150.64 1277.36,-2150.64 ; 1640.39,-2709.87 1640.39,-2467.01 1384.9,-2467.01 1384.9,-2709.53 1640.39,-2709.53 ; 280.21,-2938.73 574.94,-2938.73 574.94,-2592.46 280.21,-2592.46 280.21,-2938.73 ; 1749.07,-2963.4 2076.98,-2963.4 2076.98,-2675.8 1749.07,-2675.8 1749.07,-2963.4
  text "99" at 267.3,-170.09 h50 r270
  text "1" at 1811.81,-209.92 h50 r270
  text "RGMII" at 1050.38,-819.52 h60 r270
  text "STRAP" at 1824.22,-1195.62 h68.9
  text "/" at 606.51,-1219.73 h50
  text "PU" at 1606.96,-1262.9 h59.06
  text "RX_CLK" at 1859.74,-1306.2 h68.9
  text "PD" at 1606.96,-1325.06 h59.06
  text "PU" at 1606.96,-1402.54 h59.06
  text "GPIO_3" at 1839.09,-1453.82 h68.9
  text "PD" at 1606.96,-1466.61 h59.06
  text "HSS" at 1514.54,-2676.1 h55
  text "HSS comp" at 1949.42,-2713.3 h45
  text "detect LDO" at 536.28,-2814.14 h45 r270
  text ".Layer_Name" at 341.86,-3937.58 h50
Top Paste:
  text ".Layer_Name" at 341.86,-3937.58 h60
Bottom Paste:
  text ".Layer_Name" at 341.86,-3937.58 h60
Top Solder:
  region: 711.74,-3607.1 690.58,-3607.1 690.58,-2695.12 711.74,-2695.12
  region: 1429.32,-3605.66 1410.32,-3605.66 1410.32,-2748.33 1409.32,-2747.33 1064.15,-2747.33 1064.15,-2728.76 1429.32,-2728.76
  region: 1401.46,-2692.33 1064.35,-2692.33 1064.35,-2713.33 1401.46,-2713.33
  region: 1463.4,-3606 1444.01,-3606 1444.01,-2717.78 1462.4,-2717.78
  region: 706.08,-2695.12 963.85,-2695.12 963.85,-2713.12 706.08,-2713.12
  region: 727.8,-2745.94 747.8,-2745.94 747.8,-3607.1 727.81,-3607.1
  region: 727.37,-2728.86 963.56,-2728.86 964.18,-2746.46 727.37,-2746.46
  text ".Layer_Name" at 341.86,-3937.58 h60
  text ".Layer_Name" at 341.86,-3937.58 h60
Bottom Solder:
  text ".Layer_Name" at 341.86,-3937.58 h60
Drill Guide:
  text ".Layer_Name" at 341.86,-3937.58 h60
M1 Board Outline:
  lines w1: 0,-3612.21 0,0 1883.39,0 1883.39,-197.75 1898.64,-213 1953.39,-213 1971.39,-195 1971.39,0 2114.94,0 2114.94,-3612.21 2.39,-3612.21 0,-3612.21
  text ".Layer_Name" at 341.86,-3937.58 h60
M2 Board Dimensions:
  rectangle: -5880.63,-6768.64 -5755.63,-6643.64
  rectangle: -5755.63,-6893.64 -5380.63,-6768.64
  lines w7: -5880.63,-6768.64 -4880.63,-6768.64 ; -5755.63,-6893.64 -5755.63,-6643.64 ; -5630.63,-6893.64 -5630.63,-6643.64 ; -5380.63,-6893.64 -5380.63,-6643.64 ; -5130.63,-6893.64 -5130.63,-6643.64 ; -5880.63,-6893.64 -4880.63,-6893.64 -4880.63,-6643.64 -5880.63,-6643.64 -5880.63,-6893.64
  text ".Layer_Name" at 341.86,-3937.58 h60
M3 3D STEP Top:
  text ".Layer_Name" at 341.86,-3937.58 h60
M4 3D STEP Bottom:
  text ".Layer_Name" at 341.86,-3937.58 h60
M5 Assembly Top:
  lines w10: -6172.63,-7423.81 427.37,-7423.81 ; -6172.63,-7220.48 429.37,-7220.48 ; -6172.63,-7017.14 -6172.63,-7627.14 -2167.63,-7627.14 429.37,-7627.14 429.37,-7017.14 -6172.13,-7017.14 -6172.13,-7627.14 -4596.63,-7627.14 ; -3707.63,-7627.14 -3707.63,-7017.14 ; -2440.63,-7220.48 -2440.63,-7017.14 ; -1600.63,-7220.48 -1600.63,-7017.14 ; -978.63,-7633.64 -978.63,-7430.81
  text "COMPONENTS MARKED 'DNP' SHOULD NOT BE POPULATED." at -4727.13,-6812.14 h60
  text "ASSEMBLY VARIANT:" at -4727.63,-6927.64 h60
  text ".VariantName" at -3691.63,-6927.64 h60
  text "PCB VIEWED FROM TOP SIDE" at -6109.13,-7149.31 h60
  text "BOARD #:" at -3632.63,-7149.31 h60
  text ".PRJ_Number" at -3087.13,-7149.31 h60
  text "REV:" at -2242.63,-7149.31 h60
  text ".PCB_Rev" at -1951.13,-7149.31 h60
  text "SVN REV:" at -1404.63,-7149.31 h60
  text ".VersionControl_RevNumber" at -898.63,-7149.31 h60
  text "TID #:" at -3632.63,-7352.64 h60
  text ".TID" at -3087.13,-7352.64 h60
  text "PLOT NAME =" at -6109.13,-7557.98 h60
  text ".plot_File_Name" at -5303.63,-7557.98 h60
  text "GENERATED    :" at -3630.63,-7557.98 h60
  text ".Print_Date" at -2761.13,-7557.98 h60
  text ".Print_Time" at -2032.13,-7557.98 h60
  text "TEXAS INSTRUMENTS" at -767.63,-7557.98 h60
M6 Assembly Bottom:
  lines w10: -6173.13,-7220.98 428.87,-7220.98 ; -6171.13,-7424.31 428.87,-7424.31 ; -4765.13,-7634.14 -4765.13,-7431.31 ; -4143.13,-7220.98 -4143.13,-7017.64 ; -3303.13,-7220.98 -3303.13,-7017.64 ; -2036.13,-7627.64 -2036.13,-7017.64 ; -1147.13,-7627.64 428.37,-7627.64 428.37,-7017.64 -6173.13,-7017.64 -6173.13,-7627.64 -3576.13,-7627.64 428.87,-7627.64 428.87,-7017.64
  text "COMPONENTS MARKED 'DNP' SHOULD NOT BE POPULATED." at 221.37,-6811.64 h60
  text ".VariantName" at -822.63,-6927.64 h60
  text "ASSEMBLY VARIANT:" at 216.37,-6927.64 h60
  text ".VersionControl_RevNumber" at -4845.13,-7149.81 h60
  text "SVN REV:" at -4339.13,-7149.81 h60
  text ".PCB_Rev" at -3792.63,-7149.81 h60
  text "REV:" at -3501.13,-7149.81 h60
  text ".PRJ_Number" at -2656.63,-7149.81 h60
  text "BOARD #:" at -2111.13,-7149.81 h60
  text "PCB VIEWED FROM BOTTOM SIDE" at 365.37,-7149.81 h60
  text ".TID" at -2656.63,-7353.14 h60
  text "TID #:" at -2111.13,-7353.14 h60
  text "TEXAS INSTRUMENTS" at -4976.13,-7558.48 h60
  text ".Print_Time" at -3711.63,-7558.48 h60
  text ".Print_Date" at -2982.63,-7558.48 h60
  text "GENERATED    :" at -2113.13,-7558.48 h60
  text ".plot_File_Name" at -440.13,-7558.48 h60
  text "PLOT NAME =" at 365.37,-7558.48 h60
M9 Title Sheet:
  drawing of 57 lines, arcs and shapes, not listed
  text "5" at 2150.86,1911.87 h70
  text "3" at 611.9,1902.02 h70
  text "4" at 1300.99,1884.31 h70
  text "1" at -5140.8,1542.86 h70
  text "2" at -2645.13,1542.86 h70
  text "6" at 7354.87,1542.86 h70
  text "A" at -6297.13,399.86 h70
  text "A" at 8502.87,399.86 h70
  text "B" at -6297.13,-1980.14 h70
  text "B" at 8502.87,-1980.14 h70
  text ".Layer_Name" at 341.86,-3937.58 h60
  text "C" at -6297.13,-4355.14 h70
  text "C" at 8502.87,-4355.14 h70
  text "PROJECT TITLE:" at 5462.87,-6216.14 h45
  text ".PRJ_Title" at 5512.87,-6349.47 h70
  text "DESIGNED FOR:" at 5462.87,-6517.14 h45
  text ".PRJ_Customer" at 5512.87,-6657.14 h70
  text "D" at -6297.13,-6725.14 h70
  text "D" at 8502.87,-6725.14 h70
  text "FILE NAME:" at 5462.87,-6817.14 h45
  text ".PCB_File_Name_No_Path" at 5512.87,-6937.14 h70
  text "Texas Instruments (TI) and/or its licensors do not warrant the accuracy or completeness of this specification" at 493.37,-7098.98 h45
  text "ENGINEER:" at 5462.87,-7107.14 h45
  text "LAYOUT BY:" at 6967.87,-7107.14 h45
  text "or any information contained therein. TI and/or its licensors do not warrant that this design will meet" at 448.38,-7211.65 h45
  text ".PRJ_Engineer" at 5512.87,-7262.14 h70
  text ".PCB_Layout" at 7018.37,-7262.14 h70
  text "the specifications, will be suitable for your application or fit for any particular purpose, or will operate in" at 448.38,-7324.31 h45
  text "ALTIUM DESIGNER VERSION:" at 6967.87,-7417.14 h45
  text "an implementation. TI and/or its licensors do not warrant that the design is production worthy. You should" at 448.38,-7436.98 h45
  text "completely validate and test your design implementation to confirm the system functionality for your application." at 493.37,-7549.64 h45
  text ".print_Scale" at 5512.87,-7550.47 h70
  text ".Application_BuildNumber" at 7018.37,-7550.47 h70
  text "1" at -5140.8,-7757.14 h70
  text "2" at -2645.13,-7757.14 h70
  text "3" at -155.79,-7757.14 h70
  text "4" at 2350.88,-7757.14 h70
  text "5" at 4849.87,-7757.14 h70
  text "6" at 7354.87,-7757.14 h70
M10 Fab Notes:
  drawing of 189 lines, arcs and shapes, not listed
  text "DESIGN INFORMATION" at 6501.38,-137.47 h60
  text "MIN. TRACK WIDTH:" at 5856.83,-269.6 h60
  text "8" at 6953.07,-269.59 h60
  text "MIL" at 7107.83,-269.6 h60
  text "MIN. CLEARANCE:" at 5856.83,-393.72 h60
  text "0.2" at 6893.07,-393.72 h60
  text "mm" at 7107.83,-393.72 h60
  text "MIN. VIA PAD SIZE:" at 5856.83,-517.85 h60
  text "24" at 6923.08,-517.85 h60
  text "MIL" at 7107.83,-517.85 h60
  text "0.05mm (2MIL)" at 6551.83,-647.75 h60
  text "MINIMUM ANNULAR RING" at 5527.59,-655.97 h60
  text "EXTERNAL" at 7259.83,-655.97 h60
  text "PER" at 5727.59,-766.1 h60
  text "IPC-D-275 CLASS 2 LEVEL C" at 5947.59,-766.1 h60
  text "MIL, HOLES" at 7435.83,-866.58 h60
  text "+/-" at 7043.37,-875.16 h60
  text "+/-" at 7897.37,-875.16 h60
  text "REGISTRATION TOLERANCES:" at 5527.59,-876.23 h60
  text "METAL" at 6727.37,-876.23 h60
  text "5" at 7303.57,-876.22 h60
  text "3" at 8136.57,-876.22 h60
  text "MIL" at 8252.83,-876.23 h60
  text "HOLE SIZE TOLERANCE (UNLESS OTHERWISE SPECIFIED):" at 5527.59,-974.54 h60
  text "+/-" at 7897.37,-977.41 h60
  text "3" at 8136.57,-978.47 h60
  text "MIL" at 8252.83,-978.48 h60
  text "MATERIAL:" at 5452.83,-1116.12 h60
  text "FR-4 High Tg" at 6439.27,-1244.65 h60
  text "X" at 6294.83,-1252.64 h60
  text "FR-408" at 5873.83,-1257.16 h60
  text "OTHER" at 7361.83,-1257.16 h60
  text "62 MIL (1.6mm) +/-10%" at 6193.93,-1400.19 h60
  text "X" at 6073.83,-1402.64 h60
  text "THICKNESS:" at 5527.59,-1408.41 h60
  text "OTHER" at 7478.83,-1408.41 h60
  text "TOLERANCE:" at 5527.59,-1546.72 h60
  text "X" at 6375.83,-1546.72 h60
  text "ANSI IPC-6012 TYPE 3 CLASS 2" at 6553.84,-1546.72 h60
  text "OTHER +/-" at 6553.83,-1690.91 h60
  text "BOW & TWIST:" at 5527.59,-1836.1 h60
  text "X" at 6375.83,-1836.1 h60
  text "ANSI IPC-6012 TYPE 3 CLASS 2" at 6553.84,-1836.1 h60
  text "OTHER +/-" at 6553.83,-1982.8 h60
  text "DRILLING:" at 5452.83,-2113.41 h60
  text "NC_DRILL FILES" at 7213.83,-2218.6 h60
  text "REFERENCE:" at 5527.59,-2222.54 h60
  text "X" at 6184.83,-2222.64 h60
  text "AS SHOWN" at 6362.83,-2222.54 h60
  text "X" at 7085.83,-2222.54 h60
  text "OTHER" at 7511.83,-2364.79 h60
  text "PTH COPPER THICKNESS:" at 5527.27,-2368.32 h60
  text "X" at 6666.51,-2368.32 h60
  text "20-30 um" at 6794.5,-2368.32 h60
  text "BOARD FINISH:" at 5452.83,-2515.92 h60
  text "SILKSCREEN:" at 5608.05,-2626.05 h60
  text "X" at 6565.83,-2626.05 h60
  text "TOP" at 6682.83,-2626.05 h60
  text "X" at 7075.83,-2626.05 h60
  text "BOTTOM" at 7193.83,-2626.05 h60
  text "SILKSCREEN COLOR:" at 5608.05,-2781.23 h60
  text "X" at 6564.83,-2781.23 h60
  text "WHITE" at 6682.83,-2781.23 h60
  text "OTHER" at 7193.83,-2781.23 h60
  text "X" at 6695.83,-2924.68 h60
  text "GREEN" at 6813.83,-2924.68 h60
  text "OTHER" at 7431.83,-2924.68 h60
  text "SOLDER RESIST COLOR:" at 5608.05,-2931.55 h60
  text "X" at 6695.83,-3078.93 h60
  text "MATTE" at 6813.83,-3078.93 h60
  text "SEMI-GLOSS" at 7431.37,-3079.57 h60
  text "IMMERSION GOLD (ENIG)" at 6513.83,-3251.71 h60
  text "ENEPIG" at 7851.37,-3258.93 h60
  text "SURFACE FINISH:" at 5452.83,-3259.93 h60
  text "X" at 6335.83,-3259.93 h60
  text "IMM. TIN/SILVER OR EQUIV" at 5782.37,-3397.24 h60
  text "OTHER" at 7213.83,-3401.18 h60
  text "ARRAY/PANEL:" at 5452.83,-3556.56 h60
  text "CUT AND TRIM PER M1 BOARD OUTLINE" at 6513.83,-3564.78 h60
  text "N.C. ROUTE" at 6513.83,-3700.75 h60
  text "V. SCORE" at 7379.83,-3700.75 h60
  text "CERTIFICATION:" at 5452.83,-3829.87 h60
  text "MATERIALS AND WORKMANSHIP FOR ALL PCBS" at 6177.83,-3829.87 h60
  text "TO MEET OR EXCEED THE REQUIREMENTS OF:" at 6177.83,-3923.94 h60
  text ".Layer_Name" at 341.86,-3937.58 h60
  text "X" at 5815.33,-4052.56 h60
  text "ANSI IPC-A-600F CLASS ->" at 5943.33,-4052.56 h60
  text "X" at 7591.33,-4052.56 h60
  text "2" at 7701.33,-4052.56 h60
  text "1" at 7386.33,-4054.06 h60
  text "3" at 8055.33,-4054.06 h60
  text "X" at 6627.33,-4200.25 h60
  text "RoHS" at 6755.33,-4200.25 h60
  text "OTHER" at 7399.73,-4200.25 h60
  text "PER ORDER" at 7796.79,-4200.25 h60
  text "ALL BOARDS MUST MEET OR EXCEED UL94-V0 REQUIREMENTS." at 5480.37,-4354.08 h60
  text "PCB MUST BEAR THE UL94V-0 UL REGISTERED MATERIAL ID NUMBER" at 5480.37,-4470.14 h60
  text "ADDITIONAL REQUIREMENTS:" at 5452.83,-4639.57 h60
  text "MICROSECTION:" at 5527.59,-4746.69 h60
  text "YES" at 6433.33,-4746.69 h60
  text "REQUIRED" at 7294.83,-4891.02 h60
  text "BARE BOARD ELEC. TEST:" at 5527.59,-4893.88 h60
  text "NONE" at 6833.33,-4893.88 h60
  text "X" at 7176.83,-4893.88 h60
  text "PER ORDER" at 7886.83,-4893.88 h60
  text "XX MIL VIAS REQUIRE NON-CONDUCTIVE FILL AND PLANARIZE" at 5695.74,-5098.83 h59
  text "XX MIL VIAS REQUIRE CONDUCTIVE FILL AND PLANARIZE" at 5703.74,-5202.8 h60
  text "OUTER XX MIL TRACES REQUIRE 50 OHM SINGLE-ENDED IMPEDANCE" at 5702.76,-5366.19 h58
  text "LAYER 2 & 3 (INNER LAYERS) XX MIL WIDE, XX MIL SPACE / TRACES REQUIRE 100 OHM DIFFERENTIAL IMPEDANCE" at 5694.76,-5601.9 h60
M11 Gerber Information:
  lines w10: -6172.63,-7423.81 427.37,-7423.81 ; -6172.63,-7220.48 429.37,-7220.48 ; -6172.63,-7017.14 -6172.63,-7627.14 -2167.63,-7627.14 429.37,-7627.14 429.37,-7017.14 -6172.13,-7017.14 -6172.13,-7627.14 -4596.63,-7627.14 ; -3707.63,-7627.14 -3707.63,-7017.14 ; -2440.63,-7220.48 -2440.63,-7017.14 ; -1600.63,-7220.48 -1600.63,-7017.14 ; -978.63,-7633.64 -978.63,-7430.81
  text "ALL ARTWORK VIEWED FROM TOP SIDE" at -6109.13,-7149.31 h60
  text "BOARD #:" at -3632.63,-7149.31 h60
  text ".PRJ_Number" at -3087.13,-7149.31 h60
  text "REV:" at -2242.63,-7149.31 h60
  text ".PCB_Rev" at -1951.13,-7149.31 h60
  text "SVN REV:" at -1404.63,-7149.31 h60
  text ".VersionControl_RevNumber" at -898.63,-7149.31 h60
  text "LAYER NAME =" at -6109.13,-7352.14 h60
  text "TID #:" at -3632.63,-7352.64 h60
  text ".TID" at -3087.13,-7352.64 h60
  text "PLOT NAME =" at -6109.13,-7557.98 h60
  text ".plot_File_Name" at -5303.63,-7557.98 h60
  text "GENERATED    :" at -3630.63,-7557.98 h60
  text ".Print_Date" at -2761.13,-7557.98 h60
  text ".Print_Time" at -2032.13,-7557.98 h60
  text "TEXAS INSTRUMENTS" at -767.63,-7557.98 h60
M12 Stackup:
  drawing of 295 lines, arcs and shapes, not listed
  text "Board Layer Stack" at 4840.68,1348.45 h60
  text "Constant" at 5410.54,1348.45 h60
  text "Thickness" at 6060.38,1348.45 h60
  text "Material" at 6920.15,1348.45 h60
  text "Name" at 7859.89,1348.45 h60
  text "Layer" at 8269.8,1348.45 h60
  text "Top Overlay" at 7859.89,1228.45 h60
  text "3.5" at 5410.54,1108.45 h60
  text "0.40mil" at 6060.38,1108.45 h60
  text "Solder Resist" at 6920.15,1108.45 h60
  text "Top Solder" at 7859.89,1108.45 h60
  text "1.38mil" at 6060.38,988.45 h60
  text "CF-004" at 6920.15,988.45 h60
  text "Top Layer" at 7859.89,988.45 h60
  text "1" at 8269.8,988.45 h60
  text "4.5" at 5410.54,868.45 h60
  text "7.87mil" at 6060.38,868.45 h60
  text "PP-022" at 6920.15,868.45 h60
  text "Dielectric1" at 7859.89,868.45 h60
  text "1.38mil" at 6060.38,748.45 h60
  text "CF-004" at 6920.15,748.45 h60
  text "Signal Layer 1" at 7859.89,748.45 h60
  text "2" at 8269.8,748.45 h60
  text "4.6" at 5410.54,628.45 h60
  text "40.55mil" at 6060.38,628.45 h60
  text "Core-042" at 6920.15,628.45 h60
  text "Dielectric 2" at 7859.89,628.45 h60
  text "1.38mil" at 6060.38,508.45 h60
  text "CF-004" at 6920.15,508.45 h60
  text "Signal Layer 2" at 7859.89,508.45 h60
  text "3" at 8269.8,508.45 h60
  text "4.5" at 5410.54,388.45 h60
  text "7.87mil" at 6060.38,388.45 h60
  text "PP-022" at 6920.15,388.45 h60
  text "Dielectric 3" at 7859.89,388.45 h60
  text "1.38mil" at 6060.38,268.45 h60
  text "CF-004" at 6920.15,268.45 h60
  text "Bottom Layer" at 7859.89,268.45 h60
  text "4" at 8269.8,268.45 h60
  text "3.5" at 5410.54,148.45 h60
  text "0.40mil" at 6060.38,148.45 h60
  text "Solder Resist" at 6920.15,148.45 h60
  text "Bottom Solder" at 7859.89,148.45 h60
  text "Bottom Overlay" at 7859.89,28.45 h60
  text ".Layer_Name" at 341.86,-3937.58 h60
M13 Component Bodies Top:
  text ".Layer_Name" at 341.86,-3937.58 h60
M14 Component Bodies Bottom:
  text ".Layer_Name" at 341.86,-3937.58 h60
M15 Courtyards Top:
  text ".Layer_Name" at 341.86,-3937.58 h60
M16 Courtyards Bottom:
  text ".Layer_Name" at 341.86,-3937.58 h60
Drill Drawing:
  text ".Layer_Name" at 341.86,-3937.58 h60
M17 Embedded Cavity:
  text ".Layer_Name" at 341.86,-3937.58 h60
M18 Embedded Assembly:
  text ".Layer_Name" at 341.86,-3937.58 h60
M19 Embedded Keepout:
  text ".Layer_Name" at 341.86,-3937.58 h60

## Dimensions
-5880.63,-6893.64 to -4880.63,-6893.64 on M2 Board Dimensions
